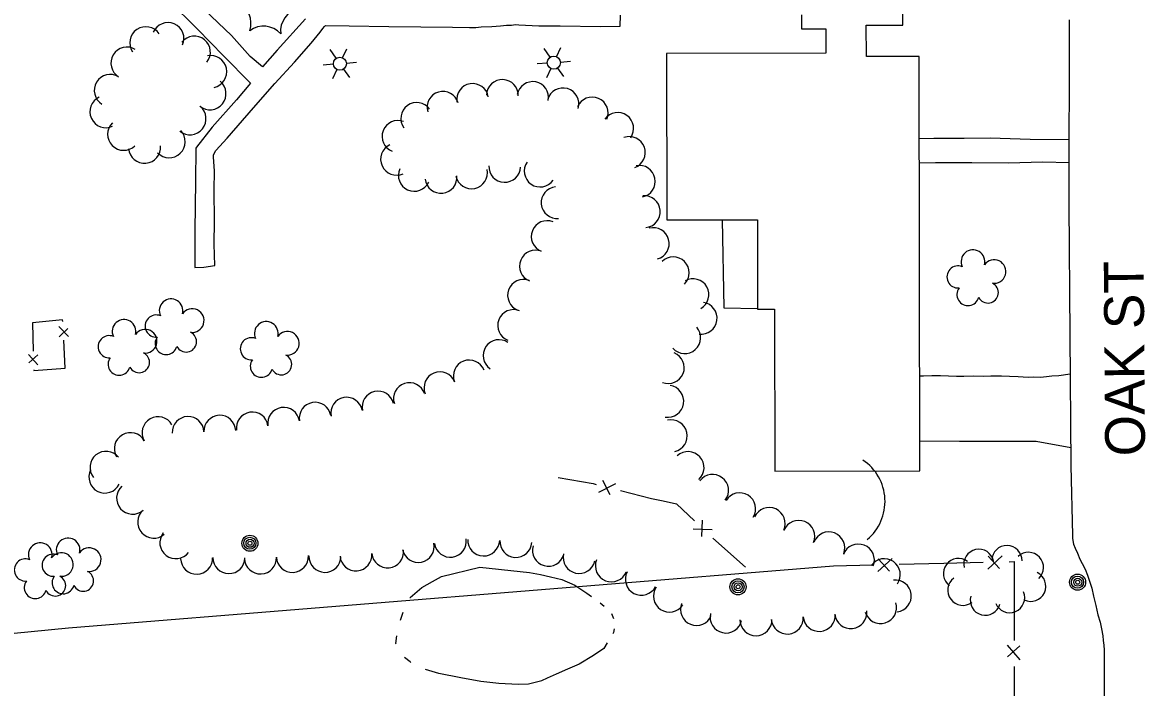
# Model space of a CAD drawing. Extents: x 189384 to 193282, y 256970 to 260388.
# Drawn here: x 190826 to 191108, y 257623.7 to 257790.7 of the extents above; entities that cross this region are included whole.
import ezdxf

# ---------------------------------------------------------------- set-up
doc = ezdxf.new("R2010")
doc.units = 0
for name, color, linetype in [('E_DWY', 7, 'Continuous'), ('E_LAND_Vegetation', 7, 'Continuous'), ('E_MISCPROP', 7, 'Continuous'), ('E_MISCPROP_HvyDash', 7, 'Continuous'), ('E_MISCPROP_HvyLine', 7, 'Continuous'), ('E_MISCPROP_Railing', 7, 'Continuous'), ('E_PATH_Sidewalk', 7, 'Continuous'), ('E_RDWY', 7, 'Continuous'), ('E_RDWY_Name', 7, 'Continuous'), ('E_WTR', 7, 'Continuous')]:
    doc.layers.add(name, color=color, linetype=linetype)

# ---------------------------------------------------------------- blocks, each defined once
blk = doc.blocks.new('CULVRT')
at = {"layer": 'E_MISCPROP_Railing'}
blk.add_arc((10, 7.5), 12.5, 216.8707, 323.1309, dxfattribs=at)
blk = doc.blocks.new('POLE_6')
at = {"layer": 'E_MISCPROP'}
for centre, radius in [((-0.01, 0.02), 2.02), ((-0.01, 0.03), 1.52), ((0, -0.01), 1.01), ((0, 0), 0.502)]:
    blk.add_circle(centre, radius, dxfattribs=at)
blk = doc.blocks.new('POLE_7')
at = {"layer": 'E_MISCPROP'}
for centre, radius in [((-0.01, 0.02), 2.02), ((-0.01, 0.03), 1.52), ((0, -0.01), 1.01), ((0, 0), 0.502)]:
    blk.add_circle(centre, radius, dxfattribs=at)
blk = doc.blocks.new('LTP_10')
at = {"layer": 'E_MISCPROP'}
for p, q in [((-0.8, 1.43), (-2, 3.73)), ((0.9, 1.42), (2.27, 3.65)), ((-1.64, 0.07), (-4.24, 0.14)), ((-0.88, -1.42), (-2.24, -3.61)), ((0.76, -1.47), (2, -3.65)), ((1.64, -0.02), (4.16, -0.09))]:
    blk.add_line(p, q, dxfattribs=at)
blk.add_circle((0, 0), 1.64, dxfattribs=at)
blk = doc.blocks.new('LTP_8')
at = {"layer": 'E_MISCPROP'}
for p, q in [((-0.8, 1.43), (-2, 3.73)), ((0.9, 1.42), (2.27, 3.65)), ((-1.64, 0.07), (-4.24, 0.14)), ((-0.88, -1.42), (-2.24, -3.61)), ((0.76, -1.47), (2, -3.65)), ((1.64, -0.02), (4.16, -0.09))]:
    blk.add_line(p, q, dxfattribs=at)
blk.add_circle((0, 0), 1.64, dxfattribs=at)
blk = doc.blocks.new('TREE_5')
at = {"layer": 'E_LAND_Vegetation'}
for centre, radius, start, end in [((-1.47, 4.28), 2.78, 1.3945, 209.1675), ((-4.47, 0.2), 2.78, 78.0716, 279.0826), ((3.57, 2.42), 2.97, 278.4236, 139.6575), ((-2.01, -4.2), 2.61, 140.7797, 358.7123), ((3.46, -3.43), 2.97, 196.0745, 79.0477)]:
    blk.add_arc(centre, radius, start, end, dxfattribs=at)
blk = doc.blocks.new('PINEL_1')
at = {"layer": 'E_LAND_Vegetation'}
for centre, start, end in [((-8.14, 7.32), 275.2112, 0.9762), ((2.26, 10.71), 215.2112, 300.9762), ((10.41, 3.41), 155.2113, 240.9762), ((-10.4, -3.39), 335.2112, 60.9762), ((8.15, -7.3), 95.2113, 180.9762), ((-2.25, -10.7), 35.2113, 120.9762)]:
    blk.add_arc(centre, 5.72, start, end, dxfattribs=at)
blk = doc.blocks.new('TREE_7')
at = {"layer": 'E_LAND_Vegetation'}
for centre, radius, start, end in [((-1.47, 4.28), 2.78, 1.3947, 209.1677), ((-4.47, 0.2), 2.78, 78.0717, 279.0828), ((3.57, 2.42), 2.97, 278.4238, 139.6577), ((-2.01, -4.2), 2.61, 140.7799, 358.7125), ((3.46, -3.43), 2.97, 196.0746, 79.0479)]:
    blk.add_arc(centre, radius, start, end, dxfattribs=at)
blk = doc.blocks.new('TREE_6')
at = {"layer": 'E_LAND_Vegetation'}
for centre, radius, start, end in [((-1.47, 4.28), 2.78, 1.3947, 209.1677), ((-4.47, 0.2), 2.78, 78.0717, 279.0828), ((3.57, 2.42), 2.97, 278.4238, 139.6577), ((-2.01, -4.2), 2.61, 140.7799, 358.7125), ((3.46, -3.43), 2.97, 196.0746, 79.0479)]:
    blk.add_arc(centre, radius, start, end, dxfattribs=at)

msp = doc.modelspace()

# ---------------------------------------------------------------- linework, layer by layer
at = {"layer": 'E_DWY'}
for points in [[(191089.08, 257702.33), (191086.22, 257701.94), (191084.47, 257701.87), (191083.11, 257701.71), (191081.64, 257701.57), (191079.76, 257701.64), (191078.54, 257701.53), (191076.02, 257701.7), (191073.86, 257701.82), (191071.8, 257701.85), (191069.18, 257701.87), (191067.22, 257701.82), (191064.86, 257701.83), (191062.42, 257701.77), (191060.57, 257701.81), (191058.53, 257701.85), (191056.53, 257701.93), (191054.37, 257701.92), (191052.22, 257701.86), (191051.33, 257701.85)], [(191089.21, 257683.85), (191080.53, 257685.49), (191061.33, 257685.45), (191051.36, 257685.52)], [(190307.65, 257339.7), (190336.95, 257405.99), (190371.25, 257481.51), (190412.4, 257575.11), (190426.44, 257606.63), (190736.05, 257628.66), (190837.56, 257638.62), (191029.69, 257654.26)]]:
    msp.add_lwpolyline(points, dxfattribs=at)
at = {"layer": 'E_LAND_Vegetation'}
for centre, radius, start, end in [((190862.52, 257786.65), 4.03, 336.5725, 156.5572), ((190856.96, 257785.61), 4.03, 33.9251, 213.9098), ((190869.16, 257783.23), 4.03, 321.2233, 141.208), ((190852.24, 257780.49), 4.03, 58.665, 238.6497), ((190873.26, 257778.35), 4.03, 282.0674, 102.0521), ((190848.05, 257773.61), 4.03, 58.665, 238.6497), ((190946.52, 257772.37), 3.99, 358.3469, 178.3316), ((190873.09, 257772.8), 4.03, 230.8564, 50.8411), ((190939.03, 257771.37), 3.99, 9.2543, 189.2389), ((190954.12, 257771.85), 3.99, 349.2176, 169.2023), ((190961.71, 257770.26), 3.99, 343.5105, 163.4952), ((190846.95, 257768.31), 4.03, 114.8992, 294.8839), ((190925, 257766.61), 3.99, 36.164, 216.1487), ((190931.58, 257769.4), 3.99, 16.3515, 196.3362), ((190969.08, 257767.96), 3.99, 336.9753, 156.9599), ((190868.06, 257766.52), 4.03, 230.6621, 50.6468), ((190975.48, 257764.09), 3.99, 324.4725, 144.4572), ((190851.41, 257762.62), 4.03, 134.4512, 314.4359), ((190920.28, 257762.1), 3.99, 69.3107, 249.2954), ((190862.82, 257760.75), 4.03, 223.9626, 43.9473), ((190856.65, 257759.36), 4.03, 185.0795, 5.0642), ((190919.92, 257756.35), 3.99, 114.7325, 294.7172), ((190978.4, 257758.04), 3.99, 289.8549, 109.8395), ((190924.38, 257752.29), 3.99, 155.3881, 335.3728), ((190938.75, 257752.94), 3.99, 192.4058, 12.3905), ((190947.09, 257754.56), 3.99, 177.5263, 357.511), ((190956, 257753.37), 3.99, 145.0167, 325.0014), ((190980.9, 257750.8), 3.99, 281.5725, 101.5572), ((190931.1, 257751.79), 3.99, 186.2889, 6.2735), ((190960.25, 257745.45), 3.99, 95.5511, 275.5358), ((190982.16, 257743.17), 3.99, 275.2584, 95.243), ((190957.75, 257736.93), 3.99, 68.3719, 248.3566), ((190984.4, 257735.17), 3.99, 284.958, 104.9427), ((190954.81, 257729.52), 3.99, 68.3719, 248.3566), ((190989.42, 257727.82), 3.99, 315.0175, 135.0022), ((190951.81, 257722.19), 3.99, 69.6178, 249.6025), ((190994.38, 257722.34), 3.99, 299.4149, 119.3995), ((190996.44, 257716.4), 3.99, 262.179, 82.1637), ((190949.34, 257714.59), 3.99, 68.911, 248.8957), ((190992.31, 257711.54), 3.99, 221.5407, 41.5254), ((190945.67, 257707.03), 3.99, 55.7373, 235.722), ((190938.19, 257701.92), 3.99, 21.4863, 201.471), ((190988.19, 257704.01), 3.99, 248.1004, 68.0851), ((190930.82, 257698.95), 3.99, 22.284, 202.2687), ((190923.17, 257696.23), 3.99, 18.1398, 198.1245), ((190915.28, 257694.13), 3.99, 12.4589, 192.4435), ((190988.03, 257695.56), 4.02, 261.2794, 81.2641), ((190899.49, 257691.32), 3.99, 9.5961, 189.5808), ((190907.4, 257692.56), 3.99, 10.5897, 190.5744), ((190860.05, 257687.66), 4.02, 29.9602, 209.9448), ((190867.59, 257687.74), 3.99, 2.2697, 182.2544), ((190875.55, 257688.05), 3.99, 2.2697, 182.2544), ((190883.7, 257688.85), 3.99, 8.3893, 188.374), ((190891.59, 257690.02), 3.99, 8.5997, 188.5844), ((190988.89, 257686.86), 4.02, 282.78, 102.7646), ((190853.09, 257683.65), 4.02, 29.9602, 209.9448), ((190846.98, 257678.97), 4.02, 38.9741, 218.9587), ((190993.13, 257678.9), 4.02, 312.1284, 132.1131), ((190846.69, 257676.52), 4.02, 153.5367, 333.5214), ((190999.28, 257673.16), 4.02, 322.7598, 142.7445), ((190853.65, 257671.23), 4.02, 131.442, 311.4267), ((191006.09, 257668.54), 4.02, 328.3737, 148.3584), ((190858.96, 257665.19), 4.02, 131.2456, 311.2303), ((191013.5, 257664.85), 4.02, 335.3625, 155.3472), ((191020.93, 257661.62), 4.02, 337.2779, 157.2626), ((190864.51, 257660.04), 4.02, 142.6118, 322.5965), ((190933.44, 257660.41), 4.02, 188.2761, 8.2608), ((190941.81, 257660.73), 4.02, 178.1604, 358.1451), ((190949.9, 257660.35), 4.02, 176.1041, 356.0888), ((191028.48, 257658.73), 4.02, 338.7539, 158.7386), ((190917.68, 257657.75), 4.02, 186.2071, 6.1918), ((190925.38, 257659.11), 4.02, 191.8121, 11.7968), ((190958.07, 257658.14), 4.02, 164.3157, 344.3004), ((191035.9, 257655.66), 4.02, 338.8651, 158.8498), ((191066.15, 257654.59), 3.8, 12.2602, 192.2449), ((191073.19, 257655.55), 3.8, 358.9452, 178.9299), ((190869.73, 257656.14), 4.02, 181.6808, 1.6655), ((190877.84, 257656.29), 4.02, 179.4205, 359.4051), ((190885.75, 257656.21), 4.02, 182.7683, 2.753), ((190893.77, 257656.6), 4.02, 182.7683, 2.753), ((190901.95, 257656.61), 4.02, 178.7646, 358.7493), ((190909.74, 257656.99), 4.02, 184.7501, 4.7348), ((190965.79, 257656.34), 4.02, 167.1662, 347.1508), ((190973.87, 257654.23), 4.02, 158.2027, 338.1874), ((191042.41, 257652), 4.02, 324.7853, 144.77), ((191061.03, 257652.27), 3.8, 52.9348, 232.9195), ((191078.6, 257653.82), 3.8, 313.2914, 133.2761), ((190981.4, 257650.87), 4.02, 152.226, 332.2107), ((191079.17, 257649.1), 3.8, 244.6367, 64.6213), ((191045.17, 257646.65), 4.02, 276.7683, 96.7529), ((191062.16, 257648.09), 3.8, 126.7981, 306.7827), ((190988.45, 257646.62), 4.02, 146.3219, 326.3066), ((191067.79, 257645.6), 3.8, 164.6616, 344.6463), ((191073.89, 257646.26), 3.8, 202.545, 22.5297), ((190995.25, 257643.28), 4.02, 157.861, 337.8456), ((191041.48, 257643.75), 4.02, 197.1933, 17.178), ((191002.67, 257641.37), 4.02, 167.4189, 347.4036), ((191018.05, 257641.11), 4.02, 184.622, 4.6067), ((191026.05, 257641.77), 4.02, 184.7388, 4.7235), ((191034, 257642.47), 4.02, 186.0699, 6.0546), ((191010.19, 257640.7), 4.02, 180.3027, 0.2874)]:
    msp.add_arc(centre, radius, start, end, dxfattribs=at)
at = {"layer": 'E_MISCPROP_HvyDash'}
msp.add_lwpolyline([(191001.67, 257741.13), (191002.12, 257718.99), (191010.61, 257718.86)], dxfattribs=at)
at = {"layer": 'E_MISCPROP_HvyLine'}
msp.add_lwpolyline([(191021.62, 257792.62), (191021.63, 257789.08), (191027.7, 257789.09), (191027.71, 257783.03), (190987.7, 257782.95), (190987.79, 257741.1), (191010.56, 257741.15), (191010.61, 257718.66), (191014.81, 257718.67), (191014.89, 257678), (191051.37, 257678.07), (191051.17, 257782.15), (191037.9, 257782.13), (191037.88, 257790.04), (191047.03, 257790.06), (191046.93, 257839.49)], dxfattribs=at)
at = {"layer": 'E_MISCPROP_Railing'}
for p, q in [((190837.54, 257711.79), (190835.11, 257714.3)), ((190835.24, 257711.78), (190837.38, 257713.88)), ((190827.5, 257707.29), (190829.89, 257704.71)), ((190829.82, 257707.24), (190827.61, 257705.18)), ((190970.7, 257672.77), (190974.96, 257674.93)), ((190971.63, 257675.77), (190973.5, 257672.13)), ((190994.39, 257663.55), (190999.16, 257663.36)), ((190996.66, 257665.72), (190996.52, 257661.63)), ((191040.77, 257652.79), (191044.38, 257656.09)), ((191040.86, 257656.01), (191043.71, 257652.92)), ((191068.41, 257653.42), (191072.03, 257656.72)), ((191068.51, 257656.64), (191071.35, 257653.55)), ((191073.26, 257634.28), (191076.48, 257630.59)), ((191076.48, 257634.11), (191073.33, 257631.34))]:
    msp.add_line(p, q, dxfattribs=at)
for points in [[(190836.1, 257715.56), (190836.08, 257715.98), (190828.51, 257715.26)], [(190828.51, 257715.26), (190828.72, 257708.16)], [(190836.72, 257703.85), (190836.35, 257710.9)], [(190828.86, 257703.47), (190828.86, 257703.28), (190836.74, 257703.85)], [(190960.54, 257676.41), (190969.28, 257674.87), (190970.02, 257674.68)], [(190976.2, 257673.11), (190983.94, 257671.15), (190986.86, 257670.53)], [(190986.86, 257670.53), (190990.2, 257669.83), (190994.73, 257665.55)], [(190999.39, 257661.2), (191007.58, 257653.9)], [(191057.34, 257654.89), (191067.22, 257655.12)], [(191073.75, 257655.27), (191075.01, 257655.3), (191075, 257645.31)], [(191029.69, 257654.26), (191039.57, 257654.49)], [(191046.11, 257654.64), (191057.34, 257654.89)], [(191075, 257645.31), (191074.99, 257635.43)], [(191074.99, 257628.9), (191074.98, 257617.66)]]:
    msp.add_lwpolyline(points, dxfattribs=at)
at = {"layer": 'E_PATH_Sidewalk'}
for points in [[(190862.64, 257796.23), (190869.93, 257789.03), (190876.46, 257782.32), (190883.22, 257775.44), (190879.72, 257771.24), (190873.62, 257764.37), (190869.66, 257759.42), (190869.55, 257759.13), (190869.42, 257750.73), (190869.27, 257738.44), (190869.27, 257729.18), (190871.54, 257729.25), (190874.29, 257729.64), (190874.13, 257735.02), (190874.24, 257740.83), (190874.15, 257748.64), (190874.2, 257753.34), (190873.93, 257756.96), (190873.94, 257757.44), (190874.53, 257758.51), (190877.39, 257761.64), (190884.03, 257769.26), (190889.39, 257775.38), (190894.3, 257780.72), (190898.46, 257785.48), (190900.79, 257788.3), (190901.45, 257789.16), (190901.87, 257789.73), (190902.09, 257789.98), (190908.04, 257789.84), (190917.99, 257789.7), (190926.01, 257789.58), (190934, 257789.54), (190938.27, 257789.47), (190939.87, 257789.44), (190941.19, 257789.65), (190943.82, 257789.66), (190946.02, 257789.86), (190947.56, 257790.02), (190948.76, 257790.05), (190949.83, 257790.22), (190950.65, 257790.15), (190955.7, 257789.88), (190961.02, 257789.88), (190971.14, 257789.73), (190976.07, 257789.79), (190976.18, 257792.53)], [(190897.06, 257791.66), (190889.97, 257783.72), (190886.26, 257779.54), (190883.15, 257782.16), (190878.46, 257787.42), (190871.7, 257793.89)], [(191088.81, 257761.24), (191079.08, 257761.34), (191069.03, 257761.61), (191062.47, 257761.54), (191058.05, 257761.55), (191054.87, 257761.55), (191051.21, 257761.48)], [(191088.81, 257755.48), (191082.2, 257755.6), (191073.49, 257755.37), (191064.37, 257755.41), (191057.88, 257755.43), (191055.3, 257755.45), (191051.22, 257755.36)]]:
    msp.add_lwpolyline(points, dxfattribs=at)
at = {"layer": 'E_RDWY'}
msp.add_lwpolyline([(191088.85, 257791.34), (191088.79, 257745.02), (191089.24, 257679.34), (191089.65, 257661.89), (191089.65, 257661.14), (191089.73, 257660.55), (191089.96, 257659.68), (191090.36, 257658.66), (191090.89, 257657.4), (191091.49, 257655.92), (191092.13, 257654.78), (191092.82, 257653.43), (191093.4, 257651.92), (191093.93, 257650.38), (191094.51, 257648.59), (191094.98, 257646.57), (191095.5, 257644.25), (191096.06, 257641.95), (191096.62, 257640.07), (191096.96, 257638.39), (191097.26, 257636.64), (191097.39, 257635.49), (191097.5, 257634.26), (191097.61, 257633.04), (191097.59, 257617.98)], dxfattribs=at)
at = {"layer": 'E_WTR'}
for points in [[(190923.3, 257646.25), (190923.31, 257646.26), (190926.26, 257648.75), (190928.92, 257650.31), (190931.21, 257651.58), (190940.88, 257653.88), (190950.96, 257652.83)], [(190950.96, 257652.83), (190953.32, 257652.58), (190956.05, 257652.03), (190958.59, 257651.49), (190961.44, 257650.78), (190964.67, 257649.39), (190967.73, 257647.39), (190968.89, 257646.53)], [(190971.03, 257644.94), (190972.06, 257644.1)], [(190920.89, 257640.62), (190921.57, 257642.55)], [(190973.92, 257642.22), (190974.45, 257641)], [(190974.57, 257638.43), (190974.43, 257637.45), (190974.25, 257637.16)], [(190919.84, 257634.63), (190919.79, 257634.75), (190920.04, 257636.65)], [(190972.86, 257634.89), (190971.97, 257633.49), (190969.37, 257631.68), (190965.75, 257629.53), (190962.89, 257628.27), (190960.02, 257626.98), (190957.74, 257626.04), (190956.37, 257625.36)], [(190923.55, 257629.97), (190923.33, 257630.08), (190921.91, 257631.18)], [(190956.39, 257625.36), (190953.04, 257624.48), (190950.44, 257624.41), (190945.59, 257624.67), (190941.06, 257625.15), (190936.05, 257626.1), (190930.59, 257627.18), (190927.22, 257628.16)]]:
    msp.add_lwpolyline(points, dxfattribs=at)

# ---------------------------------------------------------------- block references
at = {"layer": 'E_LAND_Vegetation'}
for name, p, xscale, yscale, rotation in [('PINEL_1', (190887.66, 257794.94), 0.9999977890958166, 0.9999977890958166, 66.02718632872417), ('TREE_5', (191065.43, 257726.39), 0.9999977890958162, 0.9999977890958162, 66.02718315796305), ('TREE_7', (190864.08, 257714.06), 0.9999977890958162, 0.9999977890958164, 66.02718674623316), ('TREE_7', (190852.27, 257708.87), 0.9999977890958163, 0.9999977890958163, 66.02718695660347), ('TREE_7', (190887.98, 257708.36), 0.9999977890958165, 0.9999977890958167, 66.02718632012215)]:
    msp.add_blockref(name, p, dxfattribs=dict(at, xscale=xscale, yscale=yscale, rotation=rotation))
for p, rotation in [((190831.22, 257652.79), 66.02694361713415), ((190838.22, 257653.99), 66.02694349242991)]:
    msp.add_blockref('TREE_6', p, dxfattribs=dict(at, rotation=rotation))
at = {"layer": 'E_MISCPROP'}
for name, p, xscale, yscale, rotation in [('LTP_10', (190905.7, 257780.35), 1.0000015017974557, 1.0000015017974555, 66.23274435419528), ('LTP_8', (190959.43, 257780.61), 1.0000015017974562, 1.000001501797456, 66.23274339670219), ('POLE_6', (190883.13, 257659.89), 1.0000015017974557, 1.0000015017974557, 66.2327447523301), ('POLE_7', (191090.97, 257650.12), 1.0000015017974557, 1.0000015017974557, 66.23274104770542), ('POLE_7', (191005.7, 257648.96), 1.000001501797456, 1.000001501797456, 66.23274256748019)]:
    msp.add_blockref(name, p, dxfattribs=dict(at, xscale=xscale, yscale=yscale, rotation=rotation))
at = {"layer": 'E_MISCPROP_Railing', "rotation": 93.14489919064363}
msp.add_blockref('CULVRT', (191038.13, 257660.83), dxfattribs=at)

# ---------------------------------------------------------------- texts
at = {"layer": 'E_RDWY_Name'}
msp.add_text('OAK ST', height=10, rotation=90.4466, dxfattribs=at).set_placement((191107.9, 257681.76))

doc.saveas('drawing.dxf')
